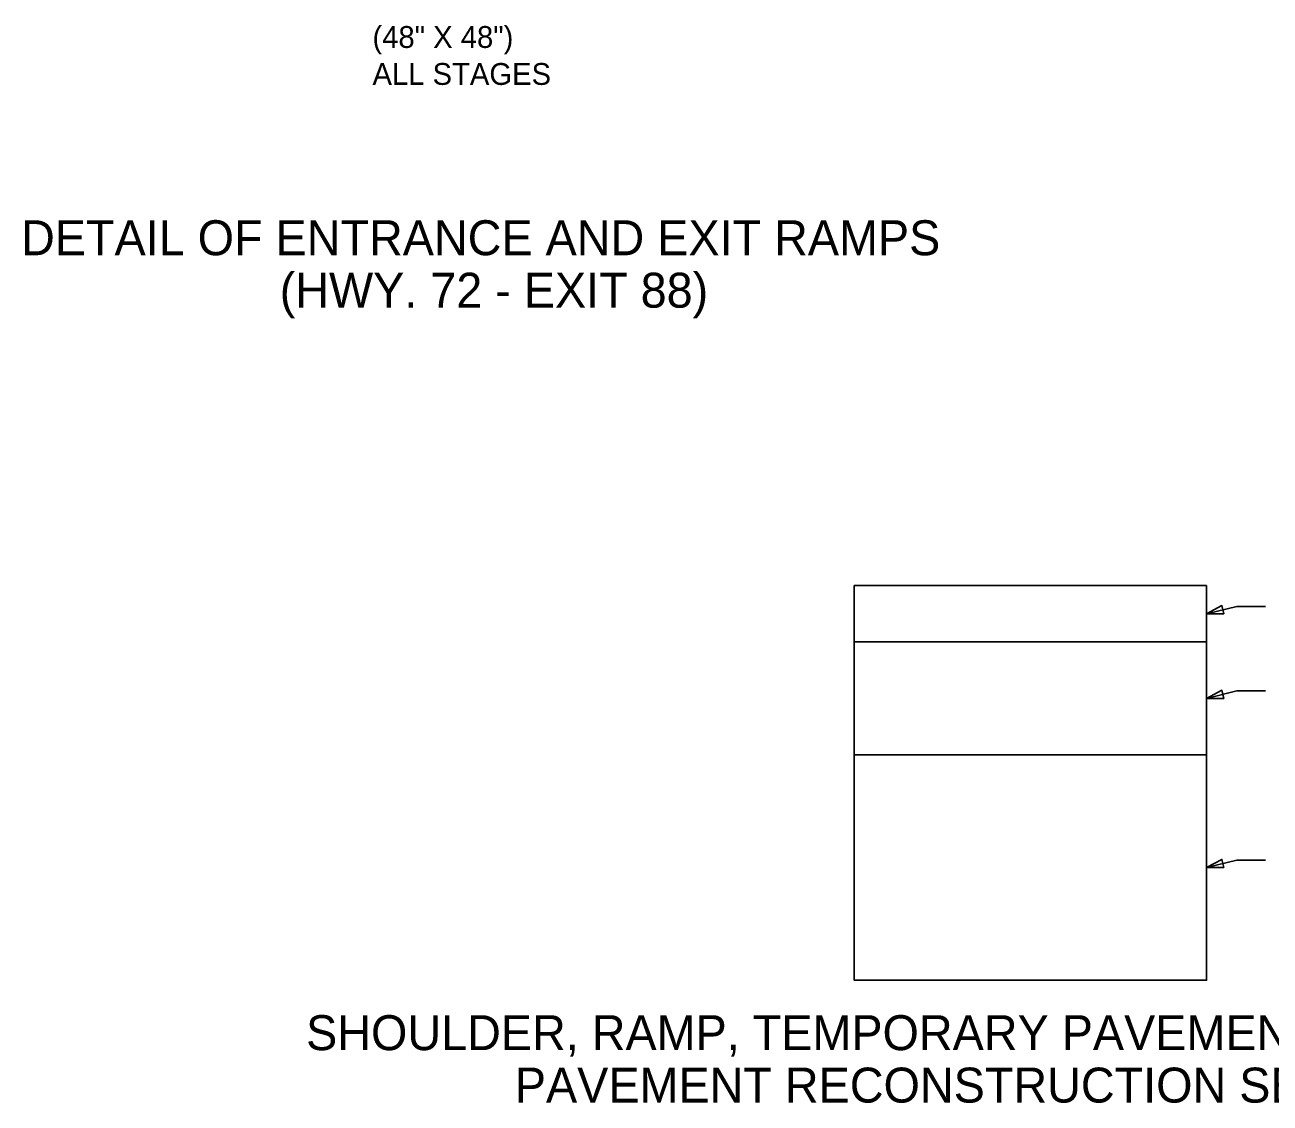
# Model space of a CAD drawing. Extents: x 1017892 to 1236694, y 658811 to 792468.
# Drawn here: x 1021486 to 1022369, y 658975 to 659740 of the extents above; entities that cross this region are included whole.
import ezdxf

# ---------------------------------------------------------------- set-up
doc = ezdxf.new("R2010")
doc.units = 0
for name, color, linetype in [('Level 8', 7, 'Continuous'), ('R_Proposed Road Annot', 7, 'Continuous'), ('S_EDGE_PAVEMENT', 7, 'Continuous')]:
    doc.layers.add(name, color=color, linetype=linetype)

msp = doc.modelspace()

# ---------------------------------------------------------------- linework, layer by layer
at = {"layer": 'R_Proposed Road Annot'}
for p, q in [((1022345.62, 659327.08), (1022365.98, 659327.08)), ((1022345.62, 659267.08), (1022365.98, 659267.08)), ((1022345.62, 659147.08), (1022365.98, 659147.08))]:
    msp.add_line(p, q, dxfattribs=at)
for points in [[(1022336.6, 659321.78), (1022324.23, 659321.84), (1022335.17, 659327.61)], [(1022074.23, 659301.84), (1022324.23, 659301.84), (1022324.23, 659221.84), (1022074.23, 659221.84)], [(1022336.6, 659261.78), (1022324.23, 659261.84), (1022335.17, 659267.61)], [(1022074.23, 659221.84), (1022324.23, 659221.84), (1022324.23, 659061.84), (1022074.23, 659061.84)], [(1022336.6, 659141.78), (1022324.23, 659141.84), (1022335.17, 659147.61)]]:
    msp.add_lwpolyline(points, close=True, dxfattribs=at)
for points in [[(1022324.23, 659321.84), (1022345.62, 659327.08)], [(1022324.23, 659261.84), (1022345.62, 659267.08)], [(1022324.23, 659141.84), (1022345.62, 659147.08)]]:
    msp.add_lwpolyline(points, dxfattribs=at)
at = {"layer": 'S_EDGE_PAVEMENT'}
for p, q in [((1022324.23, 659341.84), (1022074.23, 659341.84)), ((1022074.23, 659341.84), (1022074.23, 659301.84)), ((1022324.23, 659301.84), (1022324.23, 659341.84)), ((1022074.23, 659301.84), (1022074.23, 659221.84)), ((1022324.23, 659301.84), (1022074.23, 659301.84)), ((1022324.23, 659221.84), (1022324.23, 659301.84)), ((1022074.23, 659221.84), (1022074.23, 659061.84)), ((1022324.23, 659221.84), (1022074.23, 659221.84)), ((1022324.23, 659061.84), (1022324.23, 659221.84)), ((1022074.23, 659061.84), (1022324.23, 659061.84))]:
    msp.add_line(p, q, dxfattribs=at)

# ---------------------------------------------------------------- texts
at = {"layer": 'Level 8'}
for s, p in [('(48" X 48")', (1021732.35, 659723.28)), ('ALL STAGES', (1021732.35, 659697.05))]:
    msp.add_text(s, height=15.5, rotation=360, dxfattribs=at).set_placement(p)
for s, p in [('DETAIL OF ENTRANCE AND EXIT RAMPS', (1021482.98, 659576.2)), ('(HWY. 72 - EXIT 88)', (1021666.54, 659539)), ('SHOULDER, RAMP, TEMPORARY PAVEMENT & MAINLINE ', (1021685.25, 659012.24)), ('PAVEMENT RECONSTRUCTION SECTION', (1021833.37, 658975.04))]:
    msp.add_text(s, height=24.8, dxfattribs=at).set_placement(p)

doc.saveas('drawing.dxf')
